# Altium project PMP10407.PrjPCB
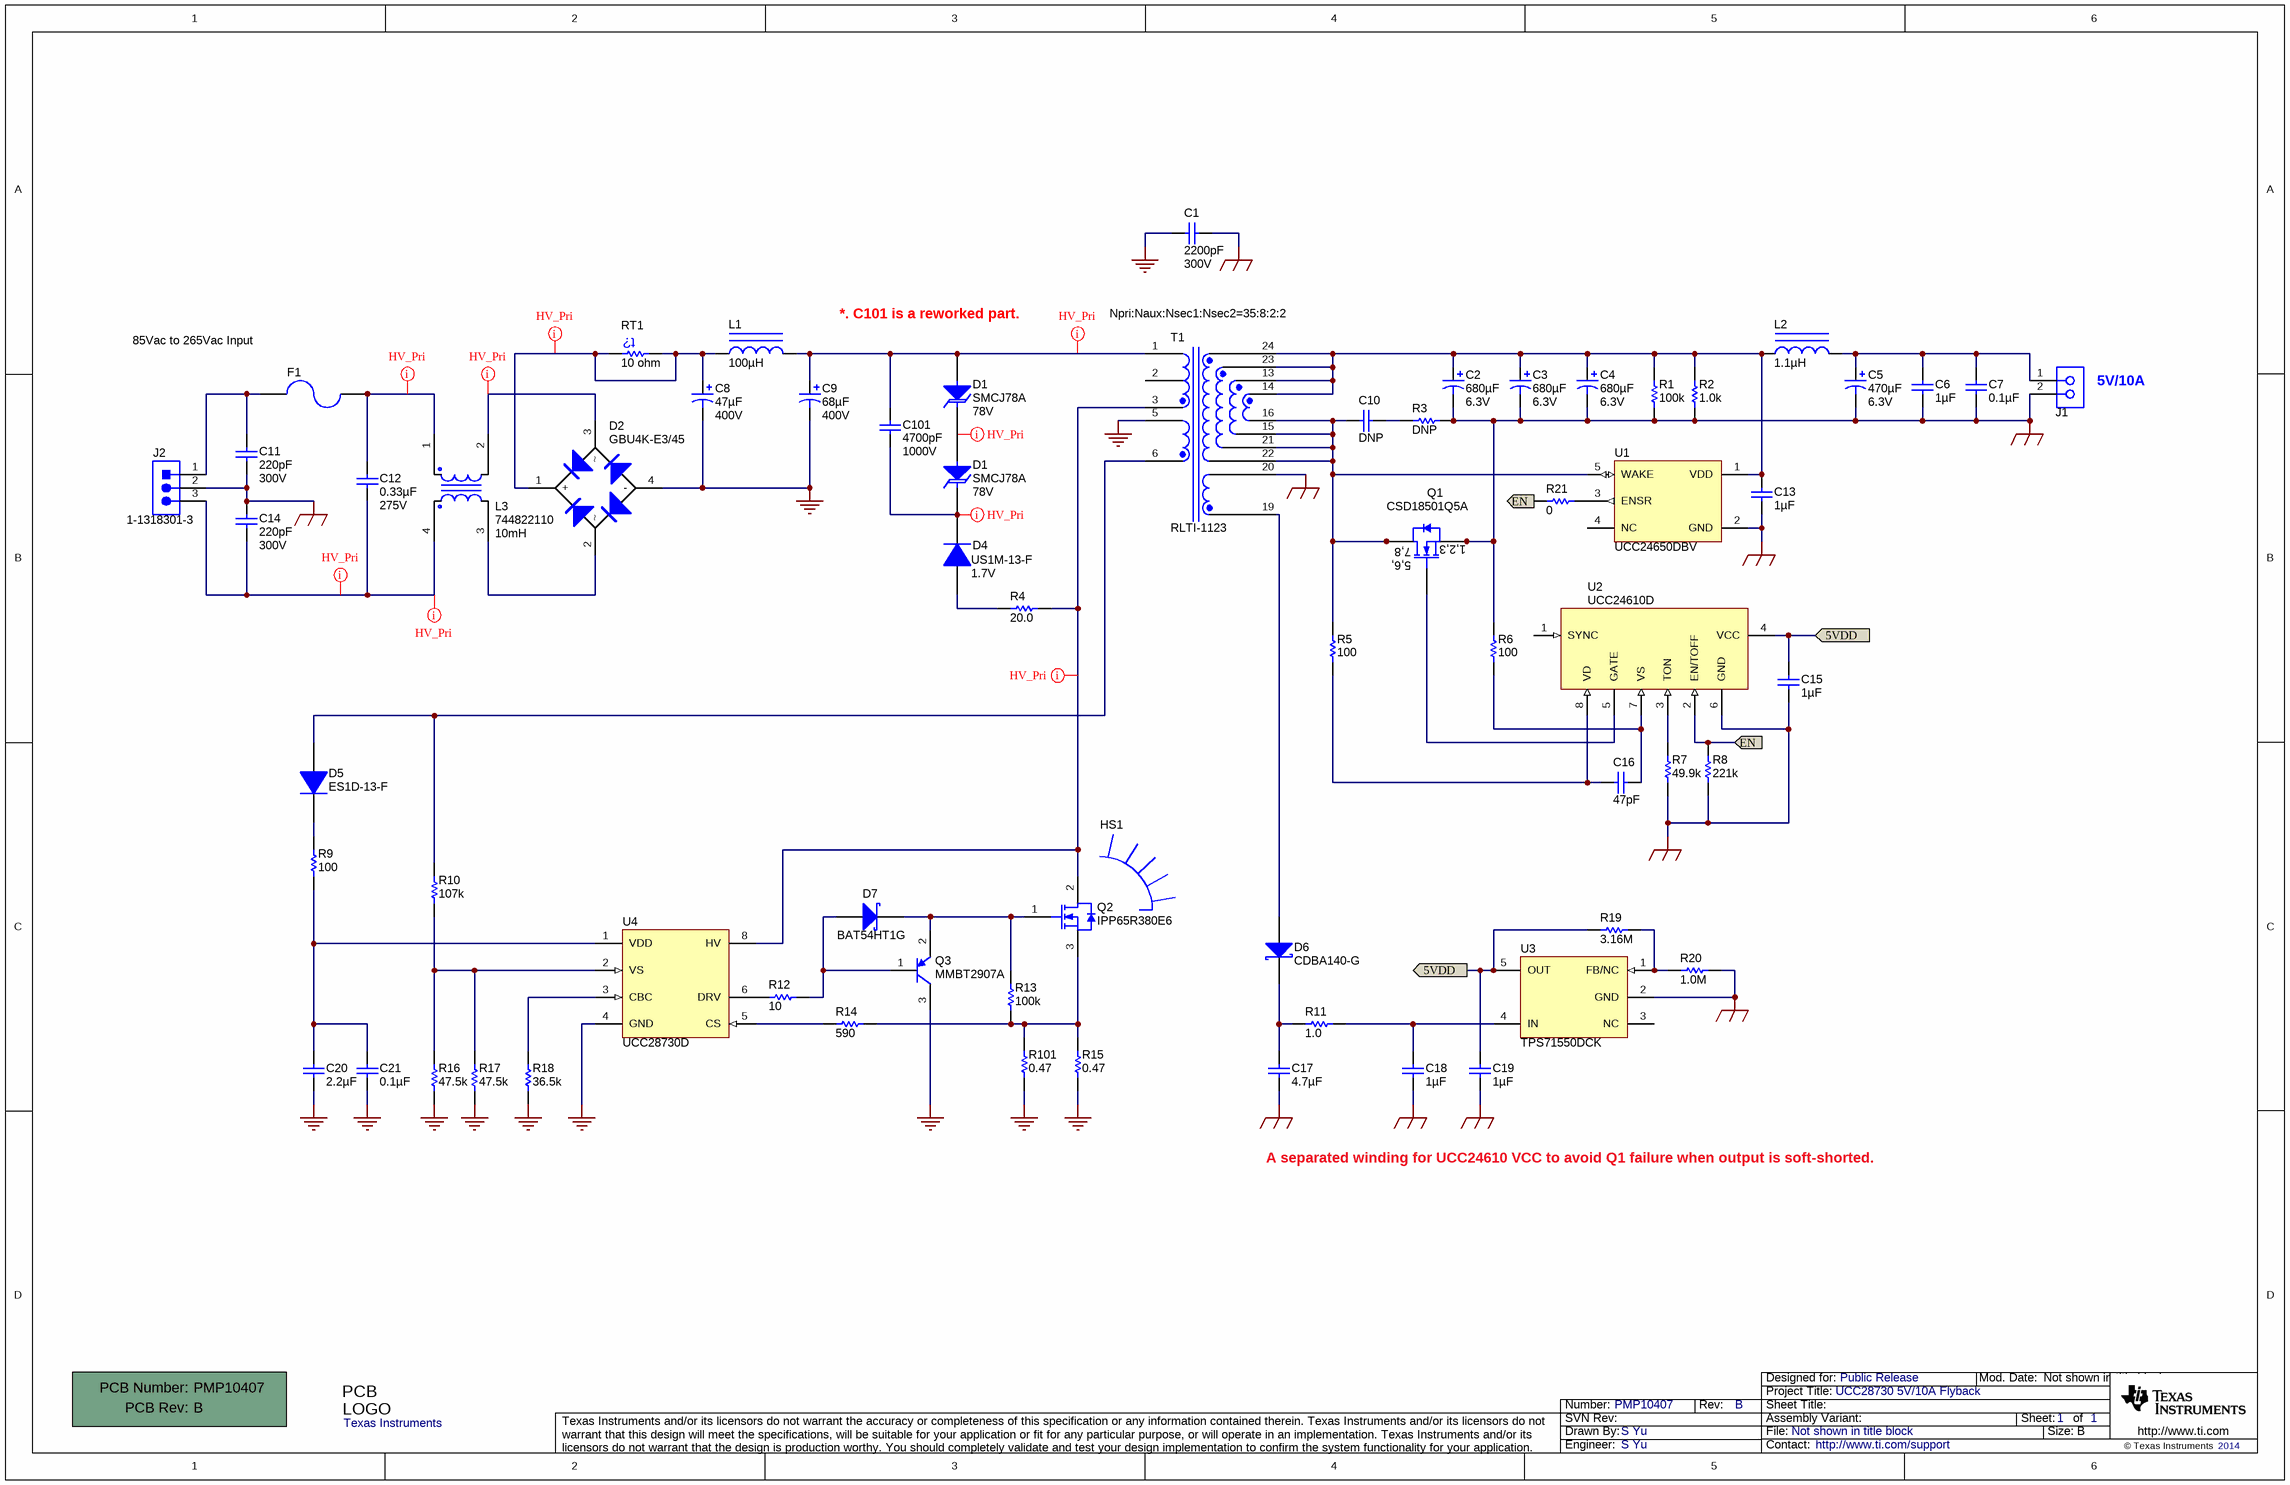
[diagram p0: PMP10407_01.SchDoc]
CopyrightYear: 2014; PCB_Layout: S Yu; PCB_Rev: B; PRJ_Customer: Public Release; PRJ_Engineer: S Yu; PRJ_Number: PMP10407; PRJ_Title: UCC28730 5V/10A Flyback; SCH_Rev: B; TechSupport: http://www.ti.com/support
1 sheet, 69 parts. Net scope: flat (ports and power ports of the same name join across sheets).
Board file: PMP10407.PcbDoc

## Sheet PMP10407_01.SchDoc
size 431 x 279 mm; Date: Not shown in title block; ApprovedBy: Not shown in title block; CheckedBy: Not shown in title block; Author: Not shown in title block; CompanyName: Not shown in title block; DrawnBy: S Yu; Engineer: Not shown in title block; Organization: Not shown in title block; Address1: Not shown in title block; Address2: Not shown in title block; Address3: Not shown in title block; Address4: Not shown in title block; DocumentNumber: 1; Revision: Use project parameter SCH_Rev; SheetNumber: 1; SheetTotal: 1; PageSetup: Record=PageOptions¦CenterHorizontal=True¦CenterVertical=True¦PrintScale=1.00¦XCorrection=1.00¦YCorrection=1.00¦PrintKind=0¦BorderSize=5000000¦LeftOffset=0¦BottomOffset=0¦Orientation=2¦PaperLength=1000¦PaperWidth=1000¦Scale=100¦PaperSource=15¦PrintQuality=600¦MediaType=1¦DitherType=10¦PaperKind=Letter¦PrintScaleMode=1

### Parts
(Parts that share a designator on the sheet are numbered #1, #2 ... from top to bottom, then left to right.)
!PCB1  Printed Circuit Board  (value not drawn)  (mechanical)
C1  ValueDisplayed: 2200pF  Value2: 300V  [E_900x700x900]  (hidden comment: DE6E3KJ222MN3A)
C2  ValueDisplayed: 680µF  Value2: 6.3V  [CAPPRD500W60D1000H1250]  (hidden comment: PLE0J681MDO1)
C3  ValueDisplayed: 680µF  Value2: 6.3V  [CAPPRD500W60D1000H1250]  (hidden comment: PLE0J681MDO1)
C4  ValueDisplayed: 680µF  Value2: 6.3V  [CAPPRD500W60D1000H1250]  (hidden comment: PLE0J681MDO1)
C5  ValueDisplayed: 470µF  Value2: 6.3V  [SEPC_C55]  (hidden comment: 6.3YXJ470M6.3X11)
C6  ValueDisplayed: 1µF  [0603]  (hidden comment: C0603C105K4PACTU)
C7  ValueDisplayed: 0.1µF  [0805_HV]  (hidden comment: 08053C104KAT2A)
C8  ValueDisplayed: 47µF  Value2: 400V  [EE_1800x2000]  (hidden comment: EKXG401ELL470MM20S)
C9  ValueDisplayed: 68µF  Value2: 400V  [EE_1800x2000]  (hidden comment: 400BXW68MEFC18X20)
C10  ValueDisplayed: DNP  [0603]  (hidden comment: C1608C0G2A101J)
C11  ValueDisplayed: 220pF  Value2: 300V  [B_800x700x800]  (hidden comment: DE6B3KJ221KN3A)
C12  ValueDisplayed: 0.33µF  Value2: 275V  [CAPRR1500W80L1750T950H1750]  (hidden comment: ECQ-U2A334ML)
C13  ValueDisplayed: 1µF  [0603]  (hidden comment: C0603C105K4PACTU)
C14  ValueDisplayed: 220pF  Value2: 300V  [B_800x700x800]  (hidden comment: DE6B3KJ221KN3A)
C15  ValueDisplayed: 1µF  [0603]  (hidden comment: C0603C105K4PACTU)
C16  ValueDisplayed: 47pF  [0402]  (hidden comment: GRM1555C1E470JA01D)
C17  ValueDisplayed: 4.7µF  [0603]  (hidden comment: 0603ZD475KAT2A)
C18  ValueDisplayed: 1µF  [0603]  (hidden comment: C0603C105K4PACTU)
C19  ValueDisplayed: 1µF  [0603]  (hidden comment: C0603C105K4PACTU)
C20  ValueDisplayed: 2.2µF  [1206]  (hidden comment: GRM316R61E225KA12D)
C21  ValueDisplayed: 0.1µF  [0603]  (hidden comment: 06035C104KAT2A)
C101  ValueDisplayed: 4700pF  Value2: 1000V  [1206]  (hidden comment: GRM31BR73A472KW01L)
D1#1  SMCJ78A  value 78V  [SMC]
D1#2  SMCJ78A  value 78V  [SMC]
D2  GBU4K-E3/45  [GBU]
D4  US1M-13-F  value 1.7V  [SMA]
D5  ES1D-13-F  [SMA]
D6  CDBA140-G  [SMA]
D7  BAT54HT1G  [sod-323]
F1  FUSE FAST 250VAC 2A RADIAL  [FUSE_372]  (value not drawn)
HS1  576012B00000G  [Aavid_530614B00000G]  (value not drawn)
J1  1715721  [PhoenixContact_1715721]  (value not drawn)
J2  1-1318301-3  [TE_1-1318301-3]
L1  ValueDisplayed: 100µH  [IND_WE-TI_8095]  (hidden comment: 744772101)
L2  ValueDisplayed: 1.1µH  [WE-HC3]  (hidden comment: 744314110)
L3  744822110  value 10mH  [IND_WE-CMB-S]
Logo1  Texas Instruments  [TI_Stacked_Overlay_Small]  (no BOM)
Q1  CSD18501Q5A  [TRANS_NexFET_Q5A]
Q2  IPP65R380E6  [TO-220AB_100mil]
Q3  MMBT2907A  [SOT-23]
R1  ValueDisplayed: 100k  [0603]  (hidden comment: CRCW0603100KJNEA)
R2  ValueDisplayed: 1.0k  [0603]  (hidden comment: CRCW06031K00JNEA)
R3  value DNP  [0805_HV]  (hidden comment: CRCW08050000Z0EA)
R4  ValueDisplayed: 20.0  [1206]  (hidden comment: CRCW120620R0FKEA)
R5  value 100  [0402]  (hidden comment: CRCW0402100RFKED)
R6  value 100  [0402]  (hidden comment: CRCW0402100RFKED)
R7  ValueDisplayed: 49.9k  [0603]  (hidden comment: CRCW060349K9FKEA)
R8  value 221k  [0603]  (hidden comment: CRCW0603221KFKEA)
R9  ValueDisplayed: 100  [1206]  (hidden comment: CRCW1206100RJNEA)
R10  ValueDisplayed: 107k  [0603]  (hidden comment: CRCW0603107KFKEA)
R11  ValueDisplayed: 1.0  [1206]  (hidden comment: CRCW12061R00JNEA)
R12  value 10  [0603]  (hidden comment: CRCW060310R0JNEA)
R13  value 100k  [0805_HV]  (hidden comment: CRCW0805100KJNEA)
R14  ValueDisplayed: 590  [0603]  (hidden comment: CRCW0603590RFKEA)
R15  ValueDisplayed: 0.47  [2010]  (hidden comment: ERJ-12ZQJR47U)
R16  ValueDisplayed: 47.5k  [0603]  (hidden comment: CRCW060347K5FKEA)
R17  ValueDisplayed: 47.5k  [0603]  (hidden comment: CRCW060347K5FKEA)
R18  ValueDisplayed: 36.5k  [0603]  (hidden comment: CRCW060336K5FKEA)
R19  ValueDisplayed: 3.16M  [0603]  (hidden comment: CRCW06033M16FKEA)
R20  ValueDisplayed: 1.0M  [0603]  (hidden comment: CRCW06031M00JNEA)
R21  ValueDisplayed: 0  [0603]  (hidden comment: CRCW06030000Z0EA)
R101  ValueDisplayed: 0.47  [2010]  (hidden comment: ERJ-12ZQJR47U)
RT1  value 10 ohm  [THERM_B57236S0]  (hidden comment: B57236S0100M000)
T1  RLTI-1123  [RENCO_RLTI-1123]
U1  UCC24650DBV  [DBV0005A_N]
U2  UCC24610D  [D0008A_N]
U3  TPS71550DCK  [DCK0005A_N]
U4  UCC28730D  [D0007A_N]

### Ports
5VDD (in), 5VDD (out), EN (in), EN (out)

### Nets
GND: C1.2 C8.2(-) C9.2(-) C20.2 C21.2 D2.4(-) Q3.3(C) R15.1 R16.1 R17.1 R18.1 R101.1 T1.5 U4.4(GND)
GND2: C1.1 C2.2(-) C3.2(-) C4.2(-) C5.2(-) C6.2 C7.2 C11.2 C13.2 C14.1 C15.2 C17.2 C18.2 C19.2 J1.2 J2.2 Q1.1(S) Q1.2(S) Q1.3(S) R1.1 R2.1 R3.2 R6.2 R7.1 R8.1 R20.1 T1.20 U1.2(GND) U2.6(GND) U3.2(GND)
5VDD: C15.1 C19.1 R19.1 U2.4(VCC) U3.5(OUT) ; port 5VDD
EN: R8.2 R21.1 U2.2(EN/TOFF) ; port EN
NetC2_1: C2.1(+) C3.1(+) C4.1(+) C13.1 L2.1 R1.2 R2.2 T1.13 T1.14 T1.23 T1.24 U1.1(VDD)
NetC5_1: C5.1(+) C6.1 C7.1 J1.1 L2.2
NetC8_1: C8.1(+) D2.1(+) L1.1 RT1.1 RT1.2
NetC9_1: C9.1(+) C101.1 D1#1.2(A) L1.2 T1.1
NetC10_1: C10.1 R3.1
NetC10_2: C10.2 Q1.5(D) Q1.6(D) Q1.7(D) Q1.8(D) Q1.9(D) R5.2 T1.15 T1.16 T1.21 T1.22 U1.5(WAKE)
NetC11_1: C11.1 F1.2 J2.1
NetC12_1: C12.1 F1.1 L3.1
NetC12_2: C12.2 C14.2 J2.3 L3.4
NetC16_1: C16.1 R5.1 U2.8(VD)
NetC16_2: C16.2 R6.1 U2.7(VS)
NetC17_1: C17.1 D6.1(K) R11.1
NetC18_1: C18.1 R11.2 U3.4(IN)
NetC20_1: C20.1 C21.1 R9.1 U4.1(VDD)
NetC101_2: C101.2 D1#2.1(K) D4.1(K)
NetD1#1_1: D1#1.1(K) D1#2.2(A)
NetD2_2: D2.2 L3.3
NetD2_3: D2.3 L3.2
NetD4_2: D4.2(A) R4.1
NetD5_1: D5.1(K) R9.2
NetD5_2: D5.2(A) R10.2 T1.6
NetD6_2: D6.2(A) T1.19
NetD7_1: D7.1(K) Q2.1(G) Q3.2(E) R13.2
NetD7_2: D7.2(A) Q3.1(B) R12.1
NetQ1_4: Q1.4(G) U2.5(GATE)
NetQ2_2: Q2.2(D) R4.2 T1.3 U4.8(HV)
NetQ2_3: Q2.3(S) R13.1 R14.2 R15.2 R101.2
NetR7_2: R7.2 U2.3(TON)
NetR10_1: R10.1 R16.2 R17.2 U4.2(VS)
NetR12_2: R12.2 U4.6(DRV)
NetR14_1: R14.1 U4.5(CS)
NetR18_2: R18.2 U4.3(CBC)
NetR19_2: R19.2 R20.2 U3.1(FB/NC)
NetR21_2: R21.2 U1.3(ENSR)

Not connected (* = marked no-connect by the designer): T1 2; U1 4(NC); U2 1(SYNC); U3 3(NC)

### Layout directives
net class HV_Pri: NetC8_1, NetC9_1, NetC12_1, NetC12_2, NetC101_2, NetD1#1_1, NetD2_3, NetQ2_2

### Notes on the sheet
- 85Vac to 265Vac Input
- *. C101 is a reworked part.
- (near T1) Npri:Naux:Nsec1:Nsec2=35:8:2:2
- (near J1) 5V/10A
- A separated winding for UCC24610 VCC to avoid Q1 failure when output is soft-shorted.

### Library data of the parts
!PCB1 = PCB: Manufacturer: Any; PartNumber: PMP10407; SymbolCreator: a0412235
C1 = DE6E3KJ222MN3A: CAP, CERM, 2200 pF, 300 V, +/- 20%, E, TH, 2- Leads, Body 9x7mm, Pin Spacing 7.5mm; Manufacturer: MuRata; Polarized: N; CompType: Capacitor; Value: 2200pF; U/M: EA; Cap_F: 0.0000000022; Tolerance_%: 20; Value1: Unknown; VDC_V: 300; TaMin_C: -40; TaMax_C: 125; Cap_Case: 9x7x9mm
C2-C4 = UVY2G4R7MPD: CAP ALUM 680UF 6.3V 20% RADIAL; Manufacturer: Nichicon; Polarized: Y; CompType: Capacitor; U/M: EA; Cap_F: 0.0000047; Tolerance_%: 20; Value1: Unknown; VDC_V: 6.3; TaMin_C: -40; TaMax_C: 105; Cap_Case: 10x12.5
C5 = 6SEPC220M: CAP ALUM 470UF 6.3V 20% RADIAL; Manufacturer: Rubycon; Polarized: Y; CompType: Capacitor; U/M: EA; Cap_F: 0.00022; Tolerance_%: 20; Value1: 0.018 ohm; VDC_V: 6.3; ESR_ohm: 0.018; IRMS_A: 2.98; TaMin_C: -55; TaMax_C: 105; Cap_Case: 6.3x5.5
C6 = C0603C105K4PACTU: CAP, CERM, 1 µF, 16 V, +/- 10%, X5R, 0603; Manufacturer: Kemet; Polarized: N; CompType: Capacitor; Value: 1uF; U/M: EA; Cap_F: 0.000001; Tolerance_%: 10; Value1: Unknown; VDC_V: 16; Value2: 16V; TaMin_C: -55; TaMax_C: 85
C7 = 08053C104KAT2A: CAP, CERM, 0.1uF, 25V, +/-10%, X7R, 0805; Manufacturer: AVX; Polarized: N; CompType: Capacitor; U/M: EA; Cap_F: 0.0000001; Tolerance_%: 10; ESR_Ohm: 0.28; Value1: 0.28 ohm; VDC_V: 25; TaMin_C: -55; TaMax_C: 125; Cap_Case: 0805
C8 = EEU-EE2G470S: CAP ALUM 47UF 400V 20% RADIAL; Manufacturer: UCC; Polarized: Y; CompType: Capacitor; U/M: EA; Cap_F: 0.000047; Tolerance_%: 20; Value1: Unknown; VDC_V: 400; IRMS_A: 1.18; TaMin_C: -25; TaMax_C: 105; Cap_Case: 18x20
C9 = EEU-EE2G470S: CAP ALUM 68UF 400V 20% RADIAL; Manufacturer: Rubycon; Polarized: Y; CompType: Capacitor; U/M: EA; Cap_F: 0.000047; Tolerance_%: 20; Value1: Unknown; VDC_V: 400; IRMS_A: 1.18; TaMin_C: -25; TaMax_C: 105; Cap_Case: 18x20
C10 = C1608C0G2A101J: CAP, CERM, 100pF, 100V, +/-5%, C0G/NP0, 0603; Manufacturer: TDK; Polarized: N; CompType: Capacitor; U/M: EA; Cap_F: 0.0000000001; Tolerance_%: 5; ESR_Ohm: 0.1202; Value1: 0.1202 ohm; VDC_V: 100; TaMin_C: -55; TaMax_C: 125
C11 C14 = DE6B3KJ221KN3A: CAP, CERM, 220 pF, 300 V, +/- 10%, B, TH, 2- Leads, Body 8x7mm, Pin Spacing 7.5mm; Manufacturer: MuRata; Polarized: N; CompType: Capacitor; Value: 220pF; U/M: EA; Cap_F: 0.00000000022; Tolerance_%: 10; Value1: Unknown; VDC_V: 300; TaMin_C: -40; TaMax_C: 125; Cap_Case: 8x7x8mm
C12 = ECQ-U2A334ML: CAP, Film, 0.33uF, 275V, +/-20%, TH; Manufacturer: Panasonic; Polarized: N; CompType: Capacitor; U/M: EA; Cap_F: 0.00000033; Tolerance_%: 20; Value1: Unknown; VDC_V: 275; TaMin_C: -40; TaMax_C: 100; Cap_Case: Radial,17.5x17.5x9.5mm
C13 C15 C18 C19 = C0603C105K4PACTU: CAP, CERM, 1uF, 16V, +/-10%, X5R, 0603; Manufacturer: Kemet; Polarized: N; CompType: Capacitor; U/M: EA; Cap_F: 0.000001; Tolerance_%: 10; Value1: Unknown; VDC_V: 16; TaMin_C: -55; TaMax_C: 85
C16 = GRM1555C1E470JA01D: CAP, CERM, 47pF, 25V, +/-5%, C0G/NP0, 0402; Manufacturer: MuRata; Polarized: N; CompType: Capacitor; U/M: EA; Cap_F: 0.000000000047; Tolerance_%: 5; Value1: Unknown; VDC_V: 25; TaMin_C: -55; TaMax_C: 125
C17 = 0603ZD475KAT2A: CAP, CERM, 4.7 µF, 10 V, +/- 10%, X5R, 0603; Manufacturer: AVX; Polarized: N; CompType: Capacitor; Value: 4.7uF; U/M: EA; Cap_F: 0.0000047; Tolerance_%: 10; Value1: Unknown; Value2: 10V; TaMin_C: -55; TaMax_C: 85
C20 = GRM316R61E225KA12D: CAP, CERM, 2.2 µF, 25 V, +/- 10%, X5R, 1206; Manufacturer: MuRata; Polarized: N; CompType: Capacitor; Value: 2.2uF; U/M: EA; Cap_F: 0.0000022; Tolerance_%: 10; ESR_ohm: 0.006; Value1: 0.006 ohm; VDC_V: 25; Value2: 25V; TaMin_C: -55; TaMax_C: 85
C21 = 06035C104KAT2A: CAP, CERM, 0.1uF, 50V, +/-10%, X7R, 0603; Manufacturer: AVX; Polarized: N; CompType: Capacitor; U/M: EA; Cap_F: 0.0000001; Tolerance_%: 10; Value1: Unknown; VDC_V: 50; TaMin_C: -55; TaMax_C: 125
C101 = GRM31BR73A472KW01L: CAP, CERM, 4700 pF, 1000 V, +/- 10%, X7R, 1206; Manufacturer: MuRata; Polarized: N; CompType: Capacitor; Value: 4700pF; U/M: EA; Cap_F: 0.0000000047; Tolerance_%: 10; Value1: Unknown; VDC_V: 1000; TaMin_C: -55; TaMax_C: 125
D1#1 D1#2 = SMCJ60A: TVS DIODE 78VWM 126VC SMC; Manufacturer: Fairchild Semiconductor; U/M: EA; Power_W: 1500; Vr_V: 78; Value1: 1500W
D2 = GBU4K-E3/45: Diode, Switching-Bridge, 800V, 4A, TH; Manufacturer: Vishay-Semiconductor; U/M: EA; Vf_V: 1; Value2: 1V; Io_A: 4; Vr_V: 800; TJmax_C: 150; RJC_CperW: 4.2
D4 = US1M-13-F: Diode, Ultrafast, 1000V, 1A, SMA; Manufacturer: Diodes Inc.; U/M: EA; Vf_V: 1.7; Io_A: 1; Vr_V: 1000; TJmax_C: 150; RJC_CperW: 30
D5 = ES1D-13-F: Diode, Ultrafast, 200V, 1A, SMA; Manufacturer: Diodes Inc.; U/M: EA; Vf_V: 0.92; Value2: 0.92V; Io_A: 1; Vr_V: 200; TJmax_C: 150; RJC_CperW: 25
D6 = BYS10-45-E3/TR: DIODE SCHOTTKY 40V 1A DO214AC; Manufacturer: Comchip; U/M: EA; Vf_V: 0.5; Value: 45V; Value1: 1.5A; Value2: 0.5V; Io_A: 1.5; Vr_V: 45; TJmax_C: 150; RJC_CperW: 25
D7 = BAT54HT1G: Diode, Schottky, 30V, 0.2A, SOD-323; Manufacturer: ON Semiconductor; U/M: EA; Vf_V: 0.35; Value2: 0.35V; Io_A: 0.2; Vr_V: 30
F1 = 37215000001: PartNumber: 37012000410; Manufacturer: Littelfuse; U/M: EA; OpeningTime_100%_min: 4; OpeningTime_200%_max: 2; VDC_V: 250; MeltingTyp: 94; Vdrop: 0.08; Soldering_Wave_MaxTemp_C: 260; Soldering_Wave_MaxTime_s: 5
HS1 = 530614B00000G: Heat Sink, TO-220, TH; Manufacturer: Aavid; SymbolCreator: a0412235
J1 = 1715721: Conn Term Block, 2POS, 5.08mm, TH; Manufacturer: Phoenix Contact; Value: 2x1; CompType: Terminal Block; U/M: EA
J2 = 1-1318301-3: HEADER, .312 VERT 3POS; Manufacturer: TE Connectivity; SymbolCreator: a0799628; U/M: EA
L1 = 744772100: INDUCTOR 100UH .9A 8095 RAD; Manufacturer: Wurth Elektronik eiSos; Imax_A: 4.2; DCR_ohm: 0.02; Value1: 0.02 ohm; Material: Ferrite
L2 = 744314110: Inductor, Shielded Drum Core, Superflux, 1.1uH, 13A, 0.0032 ohm, SMD; Manufacturer: Wurth Elektronik eiSos; Ind_H: 1.1E-6; Imax_A: 13; Irms: 15A @ 50C rise; Isat: 13A @ 30% inductance drop; DCR_ohm: 0.0032
L3 = 744822301: Coupled inductor, 10mH, 1A, TH; Manufacturer: Wurth Elektronik eiSos; SymbolCreator: a0412235; Isat: 1; Tolerance_%: 30; U/M: EA
Logo1 = TI_Logo: Texas Instrument Corporate Signature; SymbolCreator: a0412235
Q1 = CSD18501Q5A: MOSFET, N-CH, 40V, 22A, SON 5x6mm; Manufacturer: Texas Instruments; Alternate Manufacturer: None; U/M: EA; ChType: N; VdsMax_V: 40; Value1: 0.0043 ohm; Rdson45_Ohm: 0.0043; Value2: 20 nC; QgTyp_nC: 20; IdsMax_A: 22
Q2 = IPP65R190CFD: MOSFET N-CH 650V 10.6A TO220; Manufacturer: Infineon Technologies; Alternate Manufacturer: None; U/M: EA; ChType: N; VdsMax_V: 650; Value1: 0.38 ohm; Rdson45_Ohm: 0.19; Value2: 68 nC; QgTyp_nC: 68; Vgs_V: 20; IdsMax_A: 17.5
Q3 = MMBT2907A, Fairchild Semiconductor: Transistor, PNP, 60V, 0.8A, SOT-23; CompType: BJT; PNP: 1; NPN: 0; Vceo_V: 60; Vcesat1_V: 1.6; Value: 1.6V; IcRated_A: 0.8; HfeMax: 300; TaMin_C: -55; TaMax_C: 150; U/M: EA
R1 = CRCW0603100KJNEA: RES, 100 k, 5%, 0.1 W, 0603; Manufacturer: Vishay-Dale; CompType: Resistor; Value: 100k; Res_ohm: 100000; Tolerance_%: 5; Power_W: 0.1; Value2: 0.1W; VDC_V: 75; TempCo: 200 ppm/C; EIA_Code: E24; U/M: EA
R2 = CRCW06031K00JNEA: RES, 1.0 k, 5%, 0.1 W, 0603; Manufacturer: Vishay-Dale; CompType: Resistor; Value: 1.0k; Res_ohm: 1000; Value_Code: 1k00; Tolerance_%: 5; Power_W: 0.1; Value2: 0.1W; VDC_V: 75; TempCo: 200 ppm/C; EIA_Code: E24; U/M: EA
R3 = CRCW08050000Z0EA: RES, 0 ohm, 5%, 0.125W, 0805; Manufacturer: Vishay-Dale; CompType: Resistor; Res_ohm: 0; Value_Code: 0000; Tolerance_%: 5; Power_W: 0.125; VDC_V: 150; TempCo: 200 ppm/C; EIA_Code: E24; U/M: EA
R4 = CRCW120620R0FKEA: RES, 20.0, 1%, 0.25 W, 1206; Manufacturer: Vishay-Dale; CompType: Resistor; Value: 20.0; Res_ohm: 20; Value_Code: 20R0; Tolerance_%: 1; Power_W: 0.25; Value2: 0.25W; VDC_V: 200; TempCo: 100 ppm/C; EIA_Code: E96; U/M: EA
R5 R6 = CRCW0402100RFKED: RES, 100 ohm, 1%, 0.063W, 0402; Manufacturer: Vishay-Dale; CompType: Resistor; Value_Code: 100R; Tolerance_%: 1; Power_W: 0.063; VDC_V: 50; TempCo: 100 ppm/C; EIA_Code: E96; U/M: EA
R7 = CRCW060349K9FKEA: RES, 49.9 k, 1%, 0.1 W, 0603; Manufacturer: Vishay-Dale; CompType: Resistor; Value: 49.9k; Res_ohm: 49900; Value_Code: 49k9; Tolerance_%: 1; Power_W: 0.1; Value2: 0.1W; VDC_V: 75; TempCo: 100 ppm/C; EIA_Code: E96; U/M: EA
R8 = CRCW0603221KFKEA: RES, 221k ohm, 1%, 0.1W, 0603; Manufacturer: Vishay-Dale; CompType: Resistor; Res_ohm: 221000; Tolerance_%: 1; Power_W: 0.1; VDC_V: 75; TempCo: 100 ppm/C; EIA_Code: E96; U/M: EA
R9 = CRCW1206100RJNEA: RES, 100, 5%, 0.25 W, 1206; Manufacturer: Vishay-Dale; CompType: Resistor; Value: 100; Value_Code: 100R; Tolerance_%: 5; Power_W: 0.25; Value2: 0.25W; VDC_V: 200; TempCo: 200 ppm/C; EIA_Code: E24; U/M: EA
R10 = CRCW0603107KFKEA: RES, 107 k, 1%, 0.1 W, 0603; Manufacturer: Vishay-Dale; CompType: Resistor; Value: 107k; Res_ohm: 107000; Tolerance_%: 1; Power_W: 0.1; Value2: 0.1W; VDC_V: 75; TempCo: 100 ppm/C; EIA_Code: E96; U/M: EA
R11 = CRCW12061R00JNEA: RES, 1.0, 5%, 0.25 W, 1206; Manufacturer: Vishay-Dale; CompType: Resistor; Value: 1.0; Res_ohm: 1; Value_Code: 1R00; Tolerance_%: 5; Power_W: 0.25; Value2: 0.25W; VDC_V: 200; TempCo: 200 ppm/C; EIA_Code: E24; U/M: EA
R12 = CRCW060310R0JNEA: RES, 10 ohm, 5%, 0.1W, 0603; Manufacturer: Vishay-Dale; CompType: Resistor; Value_Code: 10R0; Tolerance_%: 5; Power_W: 0.1; VDC_V: 75; TempCo: 200 ppm/C; EIA_Code: E24; U/M: EA
R13 = CRCW0805100KJNEA: RES, 100k ohm, 5%, 0.125W, 0805; Manufacturer: Vishay-Dale; CompType: Resistor; Res_ohm: 100000; Tolerance_%: 5; Power_W: 0.125; VDC_V: 150; TempCo: 200 ppm/C; EIA_Code: E24; U/M: EA
R14 = CRCW0603590RFKEA: RES, 590, 1%, 0.1 W, 0603; Manufacturer: Vishay-Dale; CompType: Resistor; Value: 590; Value_Code: 590R; Tolerance_%: 1; Power_W: 0.1; Value2: 0.1W; VDC_V: 75; TempCo: 100 ppm/C; EIA_Code: E96; U/M: EA
R15 R101 = CSRN2010FKR400: RES 0.47 OHM 1/2W 5% 2010 SMD; Manufacturer: Panasonic; CompType: Resistor; Value: 0.47; Value_Code: R470; Tolerance_%: 1; Value1: 1%; Value2: 1W; TempCo: 250 ppm/C; U/M: EA
R16 R17 = CRCW060347K5FKEA: RES, 47.5 k, 1%, 0.1 W, 0603; Manufacturer: Vishay-Dale; CompType: Resistor; Value: 47.5k; Res_ohm: 47500; Value_Code: 47k5; Tolerance_%: 1; Power_W: 0.1; Value2: 0.1W; VDC_V: 75; TempCo: 100 ppm/C; EIA_Code: E96; U/M: EA
R18 = CRCW060336K5FKEA: RES, 36.5 k, 1%, 0.1 W, 0603; Manufacturer: Vishay-Dale; CompType: Resistor; Res_ohm: 36500; Value: 36.5k; Value_Code: 36k5; Tolerance_%: 1; Power_W: 0.1; Value2: 0.1W; VDC_V: 75; TempCo: 100 ppm/C; EIA_Code: E96; U/M: EA
R19 = CRCW06033M16FKEA: RES, 3.16 M, 1%, 0.1 W, 0603; Manufacturer: Vishay-Dale; CompType: Resistor; Value: 3.16Meg; Res_ohm: 3160000; Value_Code: 3M16; Tolerance_%: 1; Power_W: 0.1; Value2: 0.1W; VDC_V: 75; TempCo: 100 ppm/C; EIA_Code: E96; U/M: EA
R20 = CRCW06031M00JNEA: RES, 1.0 M, 5%, 0.1 W, 0603; Manufacturer: Vishay-Dale; CompType: Resistor; Value: 1.0Meg; Res_ohm: 1000000; Value_Code: 1M00; Tolerance_%: 5; Power_W: 0.1; Value2: 0.1W; VDC_V: 75; TempCo: 200 ppm/C; EIA_Code: E24; U/M: EA
R21 = CRCW06030000Z0EA: RES, 0, 5%, 0.1 W, 0603; Manufacturer: Vishay-Dale; CompType: Resistor; Value: 0; Value_Code: 0000; Tolerance_%: 5; Power_W: 0.1; Value2: 0.1W; VDC_V: 75; TempCo: 200 ppm/C; EIA_Code: E24; U/M: EA
RT1 = B57236S0100M000: Thermistor NTC, 10 ohm, 20%, Disc_11.5mmx6mm; Manufacturer: EPCOS Inc; Tolerance_%: 20; Power_W: 2.1; TaMin_C: -55; TaMax_C: 170; U/M: EA
T1 = RLTI-1123: Transformer, 220 uH, TH; Manufacturer: Renco Electronics; SymbolCreator: Altium; DCR_Ohm: 0.12; Value: 220 uH; LeakageL: 5 uH; U/M: EA
U1 = UCC24650DBV: Voltage Droop Monitor with Wake-Up Output, DBV0005A; Alternate Manufacturer: None; Manufacturer: Texas Instruments; SymbolCreator: x0208326; CompType: IC; U/M: EA
U2 = UCC24610D: GREEN Rectifier Controller Device, D0008A; Alternate Manufacturer: None; Manufacturer: Texas Instruments; SymbolCreator: a0411947; CompType: IC; U/M: EA
U3 = TPS71533DCK: 50 mA, 24 V, 3.2-mA Supply Current Low-Dropout Linear Regulator, DCK0005A; Alternate Manufacturer: None; Manufacturer: Texas Instruments; SymbolVersion: a0799628; CompType: IC; U/M: EA
U4 = UCC28730D: Constant-Voltage Constant-Current Flyback Controller With PSR and Wake-Up Monitoring, D0007A; Alternate Manufacturer: None; Manufacturer: Texas Instruments; SymbolCreator: x0208325; CompType: IC; U/M: EA

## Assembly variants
PMP10407: not fitted C10 C16 R3 R18 R19 R20 RT1
PMP10414: not fitted C10 R3 R18 R19 R20 RT1 U1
